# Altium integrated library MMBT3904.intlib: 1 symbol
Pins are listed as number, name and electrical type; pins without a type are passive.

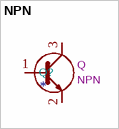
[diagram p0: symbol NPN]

## NPN
designator Q?  value NPN  Reference: Q
ki_keywords: NPN Bipolar Transistor; ki_description: Symbol for NPN BJT
footprint SOT-23 (SOT23, 3-Leads, IPC Medium Density)
pins: 1 B, 2 E, 3 C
